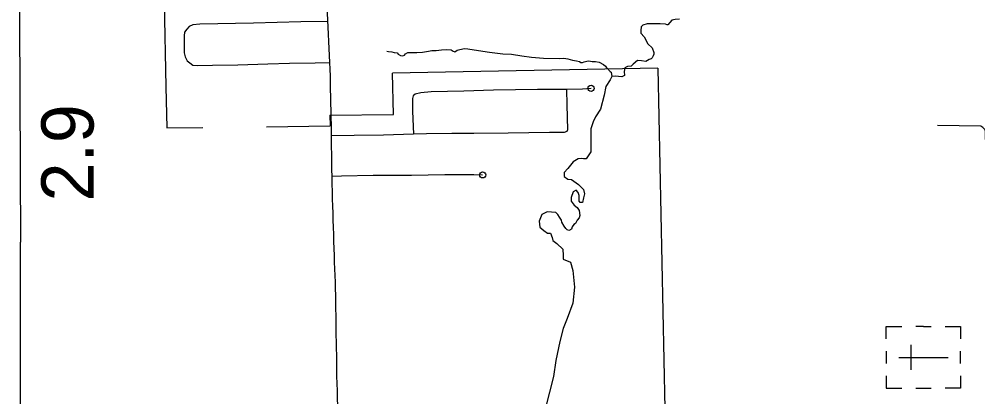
# Model space of a CAD drawing. Extents: x 1367863 to 1368197, y 380048 to 380261.
# Drawn here: x 1368012.36 to 1368042.42, y 380146.25 to 380158.09 of the extents above; entities that cross this region are included whole.
import ezdxf

# ---------------------------------------------------------------- set-up
doc = ezdxf.new("R2010")
doc.units = 0
for name, color, linetype in [('Level 10', 7, 'Continuous'), ('Level 31', 7, 'Continuous'), ('Level 32', 7, 'Continuous'), ('Level 33', 7, 'Continuous'), ('Level 35', 7, 'Continuous'), ('Level 48', 7, 'Continuous'), ('Level 57', 7, 'Continuous'), ('Level 6', 7, 'Continuous')]:
    doc.layers.add(name, color=color, linetype=linetype)

msp = doc.modelspace()

# ---------------------------------------------------------------- linework, layer by layer
at = {"layer": 'Level 10'}
for points in [[(1368015.263, 380170.542), (1368014.831, 380168.654), (1368014.522, 380167.159), (1368014.202, 380165.767), (1368013.669, 380163.66), (1368013.5, 380163.076), (1368013.325, 380162.707), (1368012.817, 380161.783), (1368012.455, 380160.97), (1368012.406, 380160.83), (1368012.362, 380160.4), (1368012.399, 380151.101)], [(1368012.815, 380129.782), (1368012.748, 380132.296), (1368012.662, 380137.381), (1368012.568, 380139.037), (1368012.466, 380139.587), (1368012.395, 380140.33), (1368012.365, 380140.567), (1368012.387, 380141.231), (1368012.409, 380145.659), (1368012.399, 380151.1)]]:
    msp.add_lwpolyline(points, dxfattribs=at)
at = {"layer": 'Level 31'}
for points in [[(1368022.004, 380158.679), (1368022.012, 380158.497), (1368022.02, 380158.279), (1368022.03, 380158.06), (1368022.04, 380157.839), (1368022.05, 380157.617), (1368022.061, 380157.392), (1368022.072, 380157.169), (1368022.082, 380156.951), (1368022.092, 380156.734), (1368022.102, 380156.519), (1368022.109, 380156.305), (1368022.114, 380156.092), (1368022.117, 380155.879), (1368022.121, 380155.664), (1368022.127, 380155.447), (1368022.131, 380155.227), (1368022.135, 380155.076)], [(1368022.032, 380158.021), (1368021.191, 380158.005), (1368019.705, 380157.966), (1368018.03, 380157.936), (1368017.803, 380157.911), (1368017.694, 380157.857), (1368017.615, 380157.778), (1368017.546, 380157.684), (1368017.531, 380157.57), (1368017.536, 380157.032), (1368017.565, 380156.913), (1368017.625, 380156.785), (1368017.714, 380156.72), (1368017.808, 380156.646), (1368017.956, 380156.636), (1368018.425, 380156.651), (1368019.22, 380156.661), (1368020.159, 380156.691), (1368020.836, 380156.706), (1368021.641, 380156.72), (1368022.093, 380156.727)]]:
    msp.add_lwpolyline(points, dxfattribs=at)
at = {"layer": 'Level 32'}
msp.add_lwpolyline([(1368043.011, 380136.212), (1368042.731, 380151.129), (1368042.659, 380154.556), (1368042.643, 380154.618), (1368042.607, 380154.662), (1368042.594, 380154.674), (1368042.578, 380154.694), (1368042.51, 380154.734), (1368041.154, 380154.752)], dxfattribs=at)
at = {"layer": 'Level 33'}
for points in [[(1368029.523, 380155.887), (1368029.53, 380155.403), (1368029.557, 380154.617), (1368029.53, 380154.569), (1368029.447, 380154.541), (1368028.985, 380154.535), (1368027.696, 380154.514), (1368026.614, 380154.5), (1368025.925, 380154.5), (1368025.132, 380154.493), (1368024.725, 380154.479), (1368023.781, 380154.452), (1368022.864, 380154.445), (1368022.145, 380154.431)], [(1368030.291, 380155.92), (1368030.021, 380155.895), (1368029.523, 380155.887), (1368028.613, 380155.886), (1368027.234, 380155.865), (1368026.304, 380155.831), (1368025.283, 380155.81), (1368024.959, 380155.783), (1368024.78, 380155.741), (1368024.718, 380155.686), (1368024.691, 380155.597), (1368024.698, 380155.21), (1368024.725, 380154.479)], [(1368022.135, 380155.076), (1368022.136, 380155.003), (1368022.142, 380154.775), (1368022.144, 380154.546), (1368022.145, 380154.317), (1368022.147, 380154.085), (1368022.15, 380153.852), (1368022.154, 380153.617), (1368022.158, 380153.382), (1368022.163, 380153.148), (1368022.167, 380152.915), (1368022.171, 380152.685), (1368022.177, 380152.457), (1368022.184, 380152.23), (1368022.191, 380152.006), (1368022.198, 380151.784), (1368022.206, 380151.563), (1368022.212, 380151.342), (1368022.22, 380151.122), (1368022.228, 380150.902), (1368022.236, 380150.685), (1368022.243, 380150.472), (1368022.251, 380150.262)], [(1368022.162, 380153.169), (1368022.471, 380153.176), (1368023.457, 380153.197), (1368024.663, 380153.197), (1368025.711, 380153.217), (1368026.614, 380153.217), (1368026.893, 380153.207)], [(1368022.251, 380150.262), (1368022.259, 380150.054), (1368022.268, 380149.846), (1368022.274, 380149.639), (1368022.278, 380149.432), (1368022.283, 380149.211), (1368022.283, 380149.004), (1368022.286, 380148.799), (1368022.287, 380148.593), (1368022.288, 380148.388), (1368022.291, 380148.184), (1368022.296, 380147.976), (1368022.302, 380147.766), (1368022.306, 380147.556), (1368022.31, 380147.334), (1368022.313, 380147.114), (1368022.316, 380146.892), (1368022.324, 380146.667), (1368022.328, 380146.439), (1368022.334, 380146.207), (1368022.339, 380145.972), (1368022.342, 380145.771)]]:
    msp.add_lwpolyline(points, dxfattribs=at)
for centre in [(1368030.291, 380155.92), (1368026.893, 380153.207)]:
    msp.add_circle(centre, 0.097, dxfattribs=at)
at = {"layer": 'Level 35'}
for points in [[(1368033.061, 380158.09), (1368032.932, 380158.083), (1368032.829, 380158.057), (1368032.694, 380157.916), (1368032.681, 380157.916), (1368032.623, 380157.929), (1368032.463, 380157.948), (1368032.366, 380157.948), (1368032.25, 380157.948), (1368032.051, 380157.948), (1368031.916, 380157.897), (1368031.858, 380157.845), (1368031.852, 380157.729), (1368031.852, 380157.652), (1368031.961, 380157.536), (1368032.07, 380157.318), (1368032.205, 380157.189), (1368032.263, 380157.047), (1368032.257, 380156.996), (1368032.238, 380156.938), (1368032.212, 380156.88), (1368032.18, 380156.842), (1368032.115, 380156.822), (1368032.006, 380156.764), (1368031.877, 380156.784), (1368031.749, 380156.79), (1368031.607, 380156.681), (1368031.549, 380156.616), (1368031.434, 380156.61), (1368031.35, 380156.559), (1368031.331, 380156.449), (1368031.337, 380156.327), (1368031.254, 380156.282), (1368031.151, 380156.288), (1368031.048, 380156.301), (1368030.945, 380156.288), (1368030.887, 380156.185), (1368030.752, 380155.98)], [(1368023.89, 380157.088), (1368023.945, 380157.077), (1368024.043, 380157.068), (1368024.123, 380157.041), (1368024.213, 380157.032), (1368024.248, 380156.987), (1368024.32, 380156.951), (1368024.392, 380156.942), (1368024.445, 380156.96), (1368024.472, 380157.005), (1368024.552, 380157.041), (1368024.83, 380157.041), (1368025.008, 380157.05), (1368025.196, 380157.086), (1368025.303, 380157.112), (1368025.438, 380157.112), (1368025.599, 380157.13), (1368025.759, 380157.139), (1368025.911, 380157.13), (1368025.965, 380157.086), (1368026.019, 380157.068), (1368026.099, 380157.121), (1368026.314, 380157.166), (1368026.43, 380157.157), (1368026.627, 380157.13), (1368027.109, 380157.059), (1368027.521, 380157.005), (1368027.798, 380156.996), (1368028.12, 380156.942), (1368028.424, 380156.898), (1368028.799, 380156.871), (1368029.309, 380156.853), (1368029.443, 380156.862), (1368029.559, 380156.844), (1368029.711, 380156.799), (1368029.836, 380156.781), (1368029.926, 380156.764), (1368029.97, 380156.728), (1368030.024, 380156.728), (1368030.078, 380156.755), (1368030.158, 380156.773), (1368030.221, 380156.781), (1368030.328, 380156.764), (1368030.426, 380156.764), (1368030.543, 380156.746), (1368030.677, 380156.665), (1368030.748, 380156.612), (1368030.766, 380156.585), (1368030.802, 380156.549), (1368030.891, 380156.451), (1368030.918, 380156.424), (1368030.945, 380156.288)], [(1368030.752, 380155.98), (1368030.701, 380155.703), (1368030.585, 380155.272), (1368030.431, 380155.027), (1368030.353, 380154.873), (1368030.283, 380154.648), (1368030.283, 380154.423), (1368030.283, 380154.275), (1368030.283, 380154.14), (1368030.283, 380154.037), (1368030.283, 380153.927), (1368030.135, 380153.709), (1368030.058, 380153.715), (1368030.006, 380153.722), (1368029.884, 380153.709), (1368029.73, 380153.612), (1368029.562, 380153.406), (1368029.453, 380153.284), (1368029.453, 380153.155), (1368029.562, 380153.078), (1368029.678, 380153.059), (1368029.897, 380152.911), (1368030.051, 380152.75), (1368030.09, 380152.609), (1368030.058, 380152.486), (1368030.019, 380152.345), (1368029.948, 380152.345), (1368029.916, 380152.384), (1368029.923, 380152.486), (1368029.923, 380152.557), (1368029.884, 380152.66), (1368029.82, 380152.731), (1368029.736, 380152.679), (1368029.665, 380152.499), (1368029.665, 380152.384), (1368029.762, 380152.255), (1368029.852, 380152.184), (1368029.923, 380152.091), (1368029.935, 380151.937), (1368029.923, 380151.866), (1368029.858, 380151.783), (1368029.807, 380151.686), (1368029.755, 380151.648), (1368029.704, 380151.583), (1368029.678, 380151.506), (1368029.646, 380151.48), (1368029.595, 380151.461), (1368029.543, 380151.48), (1368029.498, 380151.525), (1368029.453, 380151.603), (1368029.376, 380151.725), (1368029.363, 380151.789), (1368029.299, 380151.879), (1368029.247, 380151.963), (1368029.183, 380152.027), (1368028.919, 380152.046), (1368028.746, 380151.969), (1368028.662, 380151.757), (1368028.688, 380151.57), (1368028.81, 380151.467), (1368028.926, 380151.384), (1368029.016, 380151.377), (1368029.074, 380151.242), (1368029.093, 380151.146), (1368029.222, 380151.056), (1368029.408, 380150.876), (1368029.421, 380150.683), (1368029.415, 380150.567), (1368029.645, 380150.469), (1368029.718, 380150.212), (1368029.768, 380149.688), (1368029.723, 380149.181), (1368029.545, 380148.707), (1368029.417, 380148.39), (1368029.311, 380147.983), (1368029.188, 380147.392), (1368029.116, 380146.89), (1368028.859, 380145.904)]]:
    msp.add_lwpolyline(points, dxfattribs=at)
at = {"layer": 'Level 57'}
for p, q in [((1368040.712, 380148.457), (1368040.473, 380148.457)), ((1368040.712, 380148.457), (1368040.958, 380148.457)), ((1368040.324, 380147.099), (1368040.324, 380147.879)), ((1368039.548, 380147.683), (1368039.548, 380147.295)), ((1368041.877, 380147.295), (1368041.877, 380147.683)), ((1368039.936, 380147.487), (1368041.488, 380147.487)), ((1368040.712, 380147.487), (1368040.712, 380147.487)), ((1368040.712, 380147.487), (1368040.712, 380147.487)), ((1368040.473, 380146.517), (1368040.958, 380146.517))]:
    msp.add_line(p, q, dxfattribs=at)
for points in [[(1368039.548, 380148.069), (1368039.548, 380148.457), (1368040.033, 380148.457)], [(1368041.391, 380148.457), (1368041.877, 380148.457), (1368041.877, 380148.069)], [(1368039.548, 380146.905), (1368039.548, 380146.517), (1368040.033, 380146.517)], [(1368041.877, 380146.905), (1368041.877, 380146.517), (1368041.391, 380146.517)]]:
    msp.add_lwpolyline(points, dxfattribs=at)
at = {"layer": 'Level 6'}
for points in [[(1368016.907, 380158.624), (1368016.958, 380155.969)], [(1368022.104, 380155.075), (1368024.094, 380155.097), (1368024.064, 380156.401)], [(1368032.386, 380156.557), (1368024.064, 380156.401)], [(1368032.386, 380156.557), (1368032.607, 380145.868)], [(1368016.958, 380155.969), (1368016.996, 380154.68)], [(1368022.104, 380155.075), (1368022.111, 380154.742)], [(1368016.996, 380154.68), (1368018.123, 380154.693)], [(1368020.113, 380154.718), (1368022.111, 380154.742)]]:
    msp.add_lwpolyline(points, dxfattribs=at)

# ---------------------------------------------------------------- texts
at = {"layer": 'Level 48'}
msp.add_text('2.9', height=1.6394, rotation=90, dxfattribs=at).set_placement((1368014.695, 380152.376))

doc.saveas('drawing.dxf')
